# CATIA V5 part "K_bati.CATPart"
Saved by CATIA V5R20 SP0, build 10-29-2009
Part number: bati
Bounding box of the stored display mesh (mm): x -155.663 to 155.663, y 165.573 to 200, z -155.663 to 155.663
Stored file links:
  G:\Khaled_CFAO_2011\ST2M\ST2M_GR1\mponsin\Khaled\CAD_ThinkMOTION\K_bati.CATPart
  C:\Users\Socar\Documents\thinkmotion\Final\Diff2.CATProduct
  G:\Khaled_CFAO_2011\ST2M\ST2M_GR1\mponsin\Khaled\CAD_ThinkMOTION\K_mponsin.CATProduct
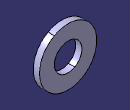
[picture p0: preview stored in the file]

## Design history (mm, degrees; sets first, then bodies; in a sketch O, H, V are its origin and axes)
Set1
  Plane1 "debut": linked copy from another document
  Line1 "axe general": linked copy from another document
Body1 (main body)
  Sketch1 on yz-plane, origin (0, 0, 0), H (0, 1, 0), V (0, 0, 1)
    line L1 (200, 74.6315) -> (165.5727, 74.6315)
    line L2 (165.5727, 74.6315) -> (165.5727, 155.663)
    line L3 (165.5727, 155.663) -> (200, 155.663)
    line L4 (200, 155.663) -> (200, 74.6315)
    reference intersected line E1 through (200, 0) direction (0, 1) from Plane1
    horizontal: L1 H, L3 H
    vertical: L2 V, L4 V
    coincidence: E1 L4
  Shaft1: profile Sketch1, axis Line1, angle 360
